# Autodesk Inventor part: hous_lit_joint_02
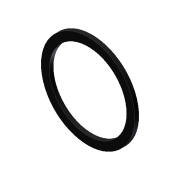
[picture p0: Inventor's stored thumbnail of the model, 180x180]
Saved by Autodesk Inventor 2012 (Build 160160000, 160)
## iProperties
Created: 2002-07
Part Number: hous_lit_joint_02
Document SubType Name: Modeling
Designer: Lieven Grauls
Stock Number: hous_lit_joint_02
Project: Valve Techcamp 2008
Density: 1 g/cm^3
Mass: 6.58984 g
Surface Area: 50.0668 cm^2
Volume: 6.58984 cm^3
Material: Default
Company: Autodesk
Control State: 0
Master: False
Checked Out: False
Shininess: 64.0
Length Units: 11269
Angle Units: 11279
Time Units: 11290
Mass Units: 11283
Length Display Precision: 3
Angle Display Precision: 2
Density: 0.0
Volumn: 0.0
Area: 0.0
PropertySet Name: Model Information
Author: Lieven Grauls
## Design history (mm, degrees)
sketch "Sketch1"
  geometry: L1 (38, 0)-(46, 0); L2 (46, 0)-(46, 4); L3 (46, 4)-(38, 4); L4 (38, 4)-(38, 0); L5 (0, 4.8)-(0, -0.8) reference; 1 further point
  constraints: 8 end point, 2 parallel, 1 horizontal, 1 horizontal alignment, 1 perpendicular
  dimensions: "d0" = 76 diameter of L4 L5; "d1" = 92 diameter of L2 L5; "d2" = 4 distance between parallel lines of L1 L3
revolve "Revolution1" sketch "Sketch1" stored, may be unused: angle "d3" = 90 deg
sketch "Sketch2"
  geometry: L1 (4, -4)-(4, -45.826); L2 (4, -4)-(45.826, -4); L3 (0, 65.888)-(0, -73.328) reference; L4 (73.328, 0)-(-65.888, 0) reference; C1 r 38 at (0, 0) reference; A1 r 46 centre (0, 0) between (4, -45.826) and (45.826, -4) reference; A2 r 46 centre (0, 0) between (4, -45.826) and (45.826, -4)
  constraints: 4 end point, 4 point on circle, 1 centre point, 1 coincident, 1 perpendicular, 1 vertical
  dimensions: "d4" = 4 distance between parallel lines of L1 L3; "d5" = 4 distance between parallel lines of L2 L4
extrude "Extrusion1" cut sketch "Sketch2" stored distance "d6" = 10; taper "d7" = 0 deg
node "Volumenkörper1"
node "Volumenkörpern"
node "Oberflächenkörpern"
